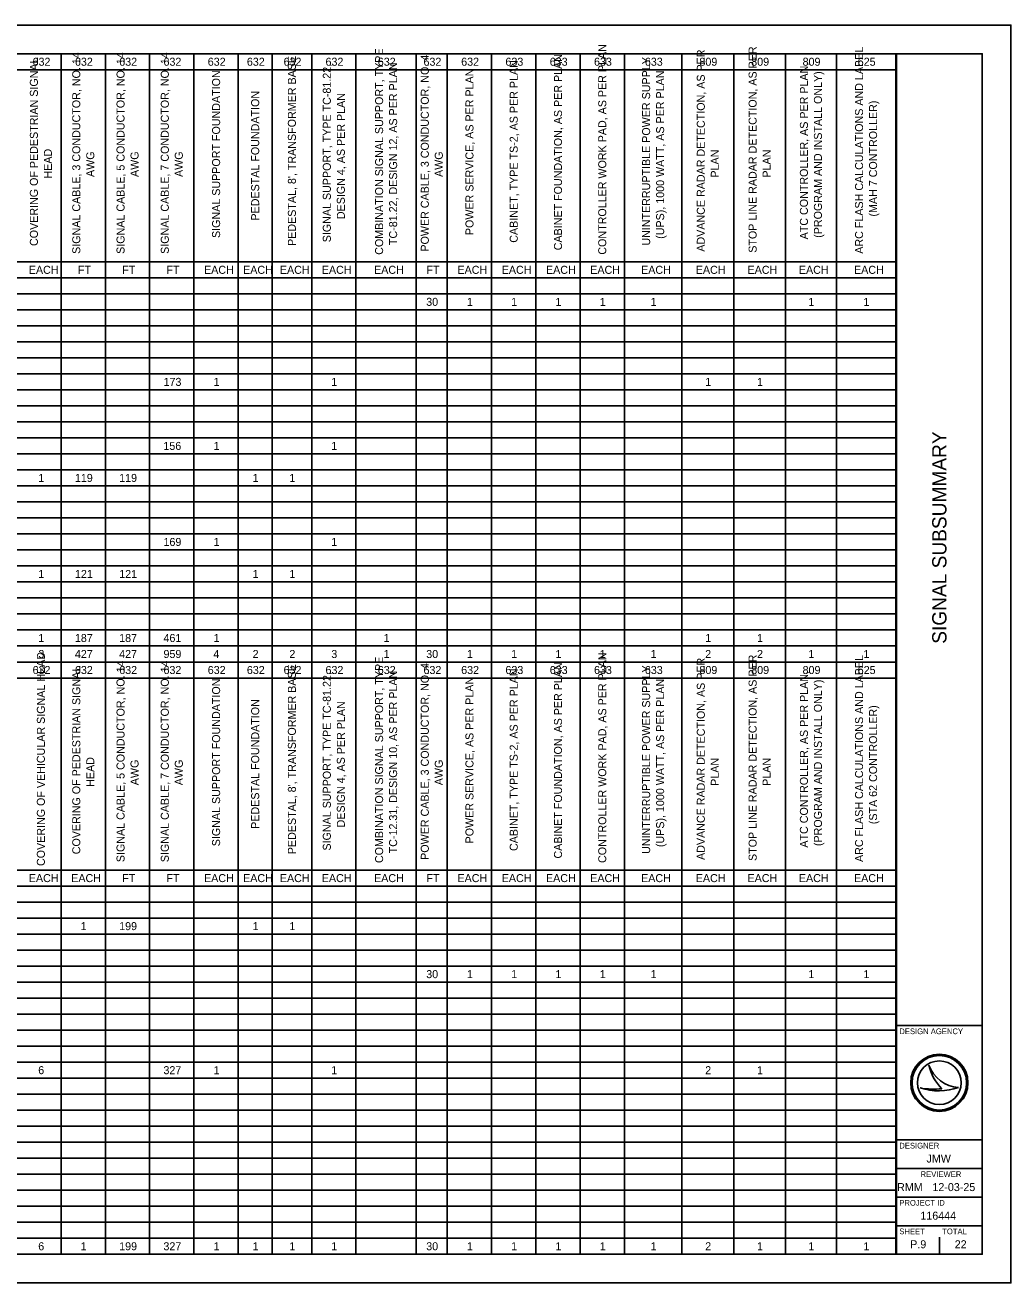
# Model space of a CAD drawing. Extents: x 0 to 34, y 0 to 22.
# Drawn here: x 16.77 to 34, y 0 to 22 of the extents above; entities that cross this region are included whole.
import ezdxf

# ---------------------------------------------------------------- set-up
doc = ezdxf.new("R2010")
doc.units = 0
for name, color, linetype in [('SH_Border', 7, 'Continuous'), ('SH_Cut_Line', 7, 'Continuous'), ('SH_Data', 7, 'Continuous'), ('SH_Text', 7, 'Continuous')]:
    doc.layers.add(name, color=color, linetype=linetype)

msp = doc.modelspace()

# ---------------------------------------------------------------- linework, layer by layer
at = {"layer": 'SH_Border'}
for p, q in [((32, 0.5), (32, 21.5)), ((32, 4.5), (33.5, 4.5)), ((32, 2.5), (33.5, 2.5)), ((32, 2), (33.5, 2)), ((32, 1.5), (33.5, 1.5)), ((32, 1), (33.5, 1))]:
    msp.add_line(p, q, dxfattribs=at)
msp.add_lwpolyline([(1.5, 21.5), (33.5, 21.5), (33.5, 0.5), (1.5, 0.5)], close=True, dxfattribs=at)
at = {"layer": 'SH_Cut_Line'}
msp.add_lwpolyline([(0, 0), (34, 0), (34, 22), (0, 22)], close=True, dxfattribs=at)
at = {"layer": 'SH_Data'}
for p, q in [((32.567, 3.81), (32.567, 3.81)), ((32.417, 3.41), (32.417, 3.41)), ((32.75, 3.5), (32.75, 3.5)), ((33.087, 3.419), (33.087, 3.419)), ((32.375, 0.675), (32.375, 0.675)), ((32.75, 0.5), (32.75, 0.8))]:
    msp.add_line(p, q, dxfattribs=at)
for radius in [0.5, 0.477, 0.477, 0.382]:
    msp.add_circle((32.75, 3.5), radius, dxfattribs=at)
for centre, radius, start, end in [((33.116, 3.998), 0.58, 198.9257, 198.9319), ((33.347, 3.97), 0.796, 191.6379, 191.6421), ((33.116, 3.998), 0.58, 198.9319, 267.1657), ((33.347, 3.97), 0.796, 191.6421, 226.0947), ((32.739, 4.37), 1.013, 251.4576, 290.0832), ((32.648, 4.654), 1.266, 259.4964, 259.4995), ((32.739, 4.37), 1.013, 251.4527, 251.4576), ((32.648, 4.654), 1.266, 259.4995, 276.6672)]:
    msp.add_arc(centre, radius, start, end, dxfattribs=at)
at = {"layer": 'SH_Text'}
for p, q in [((1.5, 21.5), (31.987, 21.5)), ((17.394, 21.5), (17.394, 10.86)), ((18.168, 21.5), (18.168, 10.86)), ((18.942, 21.5), (18.942, 10.86)), ((19.716, 21.5), (19.716, 10.86)), ((20.491, 21.5), (20.491, 10.86)), ((21.084, 21.5), (21.084, 10.86)), ((21.775, 21.5), (21.775, 10.86)), ((22.549, 21.5), (22.549, 10.86)), ((23.604, 21.5), (23.604, 10.86)), ((24.147, 21.5), (24.147, 10.86)), ((24.921, 21.5), (24.921, 10.86)), ((25.695, 21.5), (25.695, 10.86)), ((26.469, 21.5), (26.469, 10.86)), ((27.244, 21.5), (27.244, 10.86)), ((28.248, 21.5), (28.248, 10.86)), ((29.154, 21.5), (29.154, 10.86)), ((30.06, 21.5), (30.06, 10.86)), ((30.949, 21.5), (30.949, 10.86)), ((31.987, 21.5), (31.987, 10.86)), ((8.484, 21.22), (31.987, 21.22)), ((8.484, 17.86), (31.987, 17.86)), ((1.5, 17.58), (31.987, 17.58)), ((1.5, 17.3), (31.987, 17.3)), ((1.5, 17.02), (31.987, 17.02)), ((1.5, 16.74), (31.987, 16.74)), ((1.5, 16.46), (31.987, 16.46)), ((1.5, 16.18), (31.987, 16.18)), ((1.5, 15.9), (31.987, 15.9)), ((1.5, 15.62), (31.987, 15.62)), ((1.5, 15.34), (31.987, 15.34)), ((1.5, 15.06), (31.987, 15.06)), ((1.5, 14.78), (31.987, 14.78)), ((1.5, 14.5), (31.987, 14.5)), ((1.5, 14.22), (31.987, 14.22)), ((1.5, 13.94), (31.987, 13.94)), ((1.5, 13.66), (31.987, 13.66)), ((1.5, 13.38), (31.987, 13.38)), ((1.5, 13.1), (31.987, 13.1)), ((1.5, 12.82), (31.987, 12.82)), ((1.5, 12.54), (31.987, 12.54)), ((1.5, 12.26), (31.987, 12.26)), ((1.5, 11.98), (31.987, 11.98)), ((1.5, 11.7), (31.987, 11.7)), ((1.5, 11.42), (31.987, 11.42)), ((1.5, 11.14), (31.987, 11.14)), ((1.5, 10.86), (31.987, 10.86)), ((1.5, 10.86), (31.987, 10.86)), ((17.394, 10.86), (17.394, 0.5)), ((18.168, 10.86), (18.168, 0.5)), ((18.942, 10.86), (18.942, 0.5)), ((19.716, 10.86), (19.716, 0.5)), ((20.491, 10.86), (20.491, 0.5)), ((21.084, 10.86), (21.084, 0.5)), ((21.775, 10.86), (21.775, 0.5)), ((22.549, 10.86), (22.549, 0.5)), ((23.604, 10.86), (23.604, 0.5)), ((24.147, 10.86), (24.147, 0.5)), ((24.921, 10.86), (24.921, 0.5)), ((25.695, 10.86), (25.695, 0.5)), ((26.469, 10.86), (26.469, 0.5)), ((27.244, 10.86), (27.244, 0.5)), ((28.248, 10.86), (28.248, 0.5)), ((29.154, 10.86), (29.154, 0.5)), ((30.06, 10.86), (30.06, 0.5)), ((30.949, 10.86), (30.949, 0.5)), ((31.987, 10.86), (31.987, 0.5)), ((8.484, 10.58), (31.987, 10.58)), ((8.484, 7.22), (31.987, 7.22)), ((1.5, 6.94), (31.987, 6.94)), ((1.5, 6.66), (31.987, 6.66)), ((1.5, 6.38), (31.987, 6.38)), ((1.5, 6.1), (31.987, 6.1)), ((1.5, 5.82), (31.987, 5.82)), ((1.5, 5.54), (31.987, 5.54)), ((1.5, 5.26), (31.987, 5.26)), ((1.5, 4.98), (31.987, 4.98)), ((1.5, 4.7), (31.987, 4.7)), ((1.5, 4.42), (31.987, 4.42)), ((1.5, 4.14), (31.987, 4.14)), ((1.5, 3.86), (31.987, 3.86)), ((1.5, 3.58), (31.987, 3.58)), ((1.5, 3.3), (31.987, 3.3)), ((1.5, 3.02), (31.987, 3.02)), ((1.5, 2.74), (31.987, 2.74)), ((1.5, 2.46), (31.987, 2.46)), ((1.5, 2.18), (31.987, 2.18)), ((1.5, 1.9), (31.987, 1.9)), ((1.5, 1.62), (31.987, 1.62)), ((1.5, 1.34), (31.987, 1.34)), ((1.5, 1.06), (31.987, 1.06)), ((1.5, 0.78), (31.987, 0.78)), ((1.5, 0.5), (31.987, 0.5))]:
    msp.add_line(p, q, dxfattribs=at)

# ---------------------------------------------------------------- texts
at = {"layer": 'SH_Data'}
msp.add_text('SIGNAL SUBSUMMARY', height=0.25, rotation=90, dxfattribs=at).set_placement((32.875, 11.179))
for s, height, p in [('DESIGN AGENCY', 0.1, (32.05, 4.35)), ('DESIGNER', 0.1, (32.05, 2.35)), ('JMW', 0.14, (32.526, 2.105)), ('REVIEWER', 0.1, (32.422, 1.85)), ('RMM', 0.14, (32.011, 1.605)), ('12-03-25', 0.14, (32.629, 1.605)), ('PROJECT ID', 0.1, (32.05, 1.35)), ('116444', 0.14, (32.418, 1.105)), ('SHEET', 0.1, (32.05, 0.85)), ('TOTAL', 0.1, (32.8, 0.85)), ('P.9', 0.14, (32.24, 0.605)), ('22', 0.14, (33.019, 0.605))]:
    msp.add_text(s, height=height, dxfattribs=at).set_placement(p)
at = {"layer": 'SH_Text'}
for s, p in [('COMBINATION SIGNAL SUPPORT, TYPE ', (23.024, 17.983)), ('CONTROLLER WORK PAD, AS PER PLAN', (26.926, 17.985)), ('ADVANCE RADAR DETECTION, AS PER ', (28.649, 18.037)), ('STOP LINE RADAR DETECTION, AS PER ', (29.555, 18.019)), ('ARC FLASH CALCULATIONS AND LABEL ', (31.416, 18.002)), ('COVERING OF PEDESTRIAN SIGNAL ', (16.988, 18.137)), ('SIGNAL CABLE, 3 CONDUCTOR, NO. 14 ', (17.729, 17.999)), ('SIGNAL CABLE, 5 CONDUCTOR, NO. 14 ', (18.503, 17.999)), ('SIGNAL CABLE, 7 CONDUCTOR, NO. 14 ', (19.277, 17.999)), ("PEDESTAL, 8', TRANSFORMER BASE", (21.499, 18.138)), ('POWER CABLE, 3 CONDUCTOR, NO. 4 ', (23.823, 18.039)), ('CABINET, TYPE TS-2, AS PER PLAN', (25.378, 18.194)), ('CABINET FOUNDATION, AS PER PLAN', (26.152, 18.062)), ('UNINTERRUPTIBLE POWER SUPPLY ', (27.693, 18.143)), ('SIGNAL SUPPORT FOUNDATION', (20.174, 18.277)), ('SIGNAL SUPPORT, TYPE TC-81.22, ', (22.11, 18.202)), ('TC-81.22, DESIGN 12, AS PER PLAN', (23.269, 18.153)), ('POWER SERVICE, AS PER PLAN', (24.604, 18.327)), ('(UPS), 1000 WATT, AS PER PLAN', (27.938, 18.262)), ('ATC CONTROLLER, AS PER PLAN, ', (30.452, 18.253)), ('(PROGRAM AND INSTALL ONLY)', (30.697, 18.28)), ('PEDESTAL FOUNDATION', (20.857, 18.582)), ('DESIGN 4, AS PER PLAN', (22.355, 18.607)), ('(MAH 7 CONTROLLER)', (31.661, 18.652)), ('HEAD', (17.233, 19.317)), ('PLAN', (28.894, 19.334)), ('PLAN', (29.8, 19.334)), ('AWG', (17.974, 19.344)), ('AWG', (18.748, 19.344)), ('AWG', (19.522, 19.344)), ('AWG', (24.068, 19.344)), ('COVERING OF VEHICULAR SIGNAL HEAD', (17.11, 7.291)), ('CONTROLLER WORK PAD, AS PER PLAN', (26.926, 7.345)), ('COVERING OF PEDESTRIAN SIGNAL ', (17.729, 7.497)), ('SIGNAL CABLE, 5 CONDUCTOR, NO. 14 ', (18.503, 7.359)), ('SIGNAL CABLE, 7 CONDUCTOR, NO. 14 ', (19.277, 7.359)), ("PEDESTAL, 8', TRANSFORMER BASE", (21.499, 7.498)), ('COMBINATION SIGNAL SUPPORT, TYPE ', (23.024, 7.343)), ('POWER CABLE, 3 CONDUCTOR, NO. 4 ', (23.823, 7.399)), ('CABINET FOUNDATION, AS PER PLAN', (26.152, 7.422)), ('UNINTERRUPTIBLE POWER SUPPLY ', (27.693, 7.503)), ('ADVANCE RADAR DETECTION, AS PER ', (28.649, 7.397)), ('STOP LINE RADAR DETECTION, AS PER ', (29.555, 7.379)), ('ARC FLASH CALCULATIONS AND LABEL ', (31.416, 7.362)), ('SIGNAL SUPPORT, TYPE TC-81.22, ', (22.11, 7.562)), ('TC-12.31, DESIGN 10, AS PER PLAN', (23.269, 7.513)), ('POWER SERVICE, AS PER PLAN', (24.604, 7.687)), ('CABINET, TYPE TS-2, AS PER PLAN', (25.378, 7.554)), ('ATC CONTROLLER, AS PER PLAN, ', (30.452, 7.613)), ('SIGNAL SUPPORT FOUNDATION', (20.174, 7.637)), ('(UPS), 1000 WATT, AS PER PLAN', (27.938, 7.622)), ('(PROGRAM AND INSTALL ONLY)', (30.697, 7.64)), ('PEDESTAL FOUNDATION', (20.857, 7.942)), ('DESIGN 4, AS PER PLAN', (22.355, 7.967)), ('(STA 62 CONTROLLER)', (31.661, 8.023)), ('HEAD', (17.974, 8.677)), ('AWG', (18.748, 8.704)), ('AWG', (19.522, 8.704)), ('AWG', (24.068, 8.704)), ('PLAN', (28.894, 8.694)), ('PLAN', (29.8, 8.694))]:
    msp.add_text(s, height=0.14, rotation=90, dxfattribs=at).set_placement(p)
for s, p in [('632', (16.895, 21.29)), ('632', (17.636, 21.29)), ('632', (18.41, 21.29)), ('632', (19.184, 21.29)), ('632', (19.958, 21.29)), ('632', (20.642, 21.29)), ('632', (21.284, 21.29)), ('632', (22.017, 21.29)), ('632', (22.931, 21.29)), ('632', (23.73, 21.29)), ('632', (24.389, 21.29)), ('633', (25.163, 21.29)), ('633', (25.938, 21.29)), ('633', (26.712, 21.29)), ('633', (27.601, 21.29)), ('809', (28.555, 21.29)), ('809', (29.461, 21.29)), ('809', (30.359, 21.29)), ('625', (31.323, 21.29)), ('EACH', (16.829, 17.65)), ('FT', (17.688, 17.65)), ('FT', (18.462, 17.65)), ('FT', (19.236, 17.65)), ('EACH', (19.893, 17.65)), ('EACH', (20.576, 17.65)), ('EACH', (21.219, 17.65)), ('EACH', (21.952, 17.65)), ('EACH', (22.866, 17.65)), ('FT', (23.782, 17.65)), ('EACH', (24.324, 17.65)), ('EACH', (25.098, 17.65)), ('EACH', (25.872, 17.65)), ('EACH', (26.646, 17.65)), ('EACH', (27.535, 17.65)), ('EACH', (28.491, 17.65)), ('EACH', (29.396, 17.65)), ('EACH', (30.294, 17.65)), ('EACH', (31.258, 17.65)), ('30', (23.778, 17.09)), ('1', (24.489, 17.09)), ('1', (25.263, 17.09)), ('1', (26.037, 17.09)), ('1', (26.812, 17.09)), ('1', (27.701, 17.09)), ('1', (30.46, 17.09)), ('1', (31.423, 17.09)), ('173', (19.185, 15.69)), ('1', (20.059, 15.69)), ('1', (22.117, 15.69)), ('1', (28.656, 15.69)), ('1', (29.562, 15.69)), ('156', (19.182, 14.57)), ('1', (20.059, 14.57)), ('1', (22.117, 14.57)), ('1', (16.995, 14.01)), ('119', (17.635, 14.01)), ('119', (18.409, 14.01)), ('1', (20.742, 14.01)), ('1', (21.385, 14.01)), ('169', (19.184, 12.89)), ('1', (20.059, 12.89)), ('1', (22.117, 12.89)), ('1', (16.995, 12.33)), ('121', (17.636, 12.33)), ('121', (18.41, 12.33)), ('1', (20.742, 12.33)), ('1', (21.385, 12.33)), ('1', (16.995, 11.21)), ('187', (17.635, 11.21)), ('187', (18.409, 11.21)), ('461', (19.184, 11.21)), ('1', (20.059, 11.21)), ('1', (23.032, 11.21)), ('1', (28.656, 11.21)), ('1', (29.562, 11.21)), ('3', (16.996, 10.93)), ('427', (17.635, 10.93)), ('427', (18.409, 10.93)), ('959', (19.184, 10.93)), ('4', (20.056, 10.93)), ('2', (20.742, 10.93)), ('2', (21.385, 10.93)), ('3', (22.118, 10.93)), ('1', (23.032, 10.93)), ('30', (23.778, 10.93)), ('1', (24.489, 10.93)), ('1', (25.263, 10.93)), ('1', (26.037, 10.93)), ('1', (26.812, 10.93)), ('1', (27.701, 10.93)), ('2', (28.656, 10.93)), ('2', (29.562, 10.93)), ('1', (30.46, 10.93)), ('1', (31.423, 10.93)), ('632', (16.895, 10.65)), ('632', (17.636, 10.65)), ('632', (18.41, 10.65)), ('632', (19.184, 10.65)), ('632', (19.958, 10.65)), ('632', (20.642, 10.65)), ('632', (21.284, 10.65)), ('632', (22.017, 10.65)), ('632', (22.931, 10.65)), ('632', (23.73, 10.65)), ('632', (24.389, 10.65)), ('633', (25.163, 10.65)), ('633', (25.938, 10.65)), ('633', (26.712, 10.65)), ('633', (27.601, 10.65)), ('809', (28.555, 10.65)), ('809', (29.461, 10.65)), ('809', (30.359, 10.65)), ('625', (31.323, 10.65)), ('EACH', (16.829, 7.01)), ('EACH', (17.571, 7.01)), ('FT', (18.462, 7.01)), ('FT', (19.236, 7.01)), ('EACH', (19.893, 7.01)), ('EACH', (20.576, 7.01)), ('EACH', (21.219, 7.01)), ('EACH', (21.952, 7.01)), ('EACH', (22.866, 7.01)), ('FT', (23.782, 7.01)), ('EACH', (24.324, 7.01)), ('EACH', (25.098, 7.01)), ('EACH', (25.872, 7.01)), ('EACH', (26.646, 7.01)), ('EACH', (27.535, 7.01)), ('EACH', (28.491, 7.01)), ('EACH', (29.396, 7.01)), ('EACH', (30.294, 7.01)), ('EACH', (31.258, 7.01)), ('1', (17.736, 6.17)), ('199', (18.409, 6.17)), ('1', (20.742, 6.17)), ('1', (21.385, 6.17)), ('30', (23.778, 5.33)), ('1', (24.489, 5.33)), ('1', (25.263, 5.33)), ('1', (26.037, 5.33)), ('1', (26.812, 5.33)), ('1', (27.701, 5.33)), ('1', (30.46, 5.33)), ('1', (31.423, 5.33)), ('6', (16.994, 3.65)), ('327', (19.183, 3.65)), ('1', (20.059, 3.65)), ('1', (22.117, 3.65)), ('2', (28.656, 3.65)), ('1', (29.562, 3.65)), ('6', (16.994, 0.57)), ('1', (17.736, 0.57)), ('199', (18.409, 0.57)), ('327', (19.183, 0.57)), ('1', (20.059, 0.57)), ('1', (20.742, 0.57)), ('1', (21.385, 0.57)), ('1', (22.117, 0.57)), ('30', (23.778, 0.57)), ('1', (24.489, 0.57)), ('1', (25.263, 0.57)), ('1', (26.037, 0.57)), ('1', (26.812, 0.57)), ('1', (27.701, 0.57)), ('2', (28.656, 0.57)), ('1', (29.562, 0.57)), ('1', (30.46, 0.57)), ('1', (31.423, 0.57))]:
    msp.add_text(s, height=0.14, dxfattribs=at).set_placement(p)

doc.saveas('drawing.dxf')
